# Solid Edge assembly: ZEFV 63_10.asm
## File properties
Title: Zylinder
Author: bmolnar
Template: iso metric assembly.asm
Last saved by: bmolnar
Revision: 10
Application: Solid Edge
Username: bmolnar
Dokumentum tartalom típus: 1
Document Number: ZEFV 63/10
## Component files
Kit_2.par
Kit_1.par
Kolbenstange.par
Profilrohr.par
Mutter.par
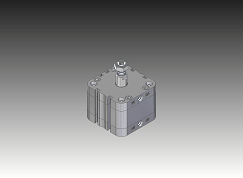
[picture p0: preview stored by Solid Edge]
